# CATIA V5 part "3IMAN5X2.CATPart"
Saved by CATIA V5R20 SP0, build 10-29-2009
Part number: 3IMAN5X2
Revision: ANY
Definition: UNKNOWN
Nomenclature: 3IMAN5X2
Source: Unknown
Bounding box of the stored display mesh (mm): x -2.5 to 2.5, y 0 to 2, z -2.5 to 2.5
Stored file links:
  C:\Users\Utente\Desktop\IO LAVORO\3D X SITO CF\CUMSA\3D files CG\CG 603035\3IMAN5X2.CATPart
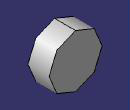
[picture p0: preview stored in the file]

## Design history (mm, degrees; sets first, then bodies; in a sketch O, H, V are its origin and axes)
Body1 "Saliente-Extruir1" (main body)
  Solid1: solid without history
